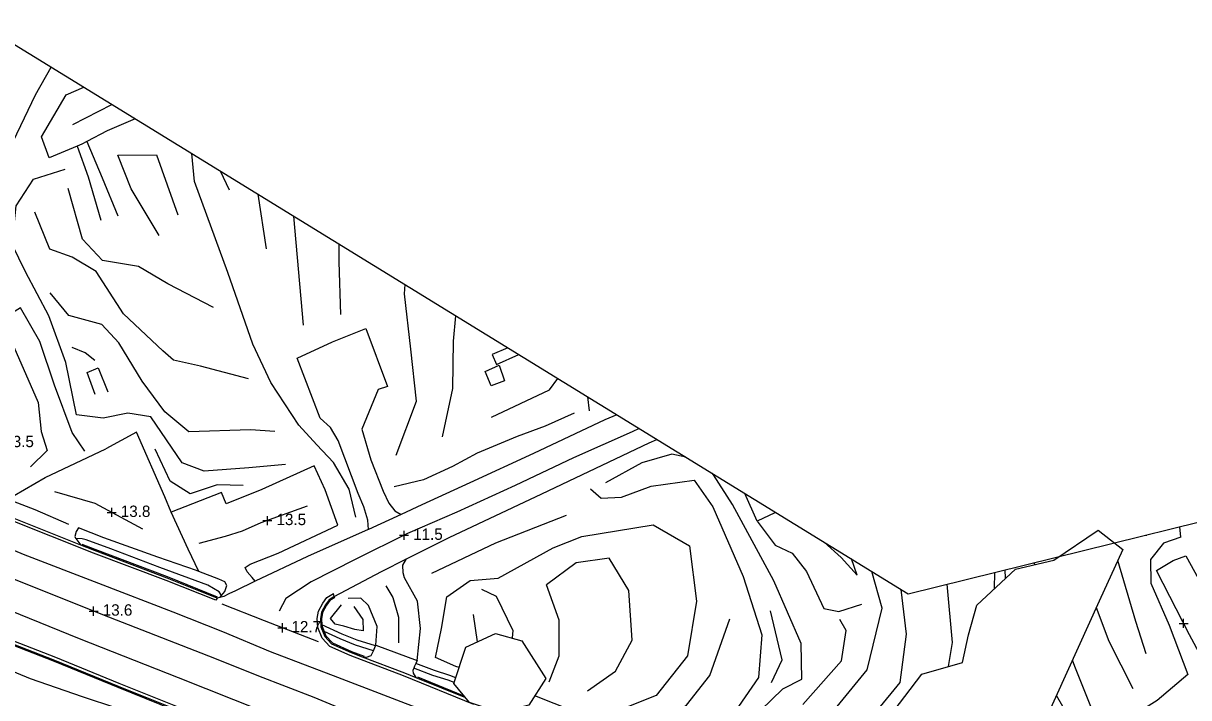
# Model space of a CAD drawing. Extents: x 2316231 to 2323598, y 363169 to 371906.
# Drawn here: x 2320328 to 2320840, y 366181 to 366478 of the extents above; entities that cross this region are included whole.
import ezdxf

# ---------------------------------------------------------------- set-up
doc = ezdxf.new("R2010")
doc.units = 0
for name, color, linetype in [('RD_DTM_BkLn1', 7, 'Continuous'), ('RD_DTM_Holes', 7, 'Continuous'), ('RD_DTM_TinHull', 7, 'Continuous'), ('RD_DTM_Void', 7, 'Continuous'), ('RD_EX_Road', 7, 'Continuous')]:
    doc.layers.add(name, color=color, linetype=linetype)

msp = doc.modelspace()

# ---------------------------------------------------------------- linework, layer by layer
at = {"layer": 'RD_DTM_BkLn1'}
for p, q in [((2320349.32, 366433.108), (2320366.601, 366441.984)), ((2320434.499, 366378.577), (2320430.846, 366402.512)), ((2320450.743, 366345.006), (2320446.543, 366392.867)), ((2320576.626, 366307.37), (2320575.799, 366313.452)), ((2320836.637, 366251.842), (2320836.128, 366256.376)), ((2320821.439, 366252.389), (2320821.41, 366252.742)), ((2320694.316, 366235.036), (2320691.728, 366242.224)), ((2320772.393, 366239.775), (2320772.082, 366240.564)), ((2320754.705, 366229.244), (2320754.75, 366236.285)), ((2320759.549, 366233.772), (2320759.337, 366237.417)), ((2320527.298, 366205.819), (2320525.602, 366217.862)), ((2320786.901, 366173.556), (2320781.929, 366182.258))]:
    msp.add_line(p, q, dxfattribs=at)
for points in [[(2320277.189, 366325.878), (2320280.846, 366330.64), (2320288.025, 366344.848), (2320297.623, 366364.721), (2320308.671, 366391.91), (2320318.365, 366415.644), (2320332.971, 366446.263), (2320339.886, 366458.398)], [(2320387.394, 366384.453), (2320375.086, 366404.966), (2320369.143, 366419.66), (2320386.201, 366419.835), (2320395.494, 366393.474)], [(2320473.779, 366260.649), (2320470.841, 366272.884), (2320464.038, 366284.668), (2320456.706, 366292.429), (2320448.785, 366301.035), (2320436.442, 366319.845), (2320428.589, 366336.629), (2320417.593, 366368.193), (2320402.945, 366408.194), (2320401.743, 366420.393)], [(2320442.845, 366283.786), (2320426.769, 366282.216), (2320407.09, 366280.857), (2320397.408, 366284.435), (2320383.722, 366304.747), (2320373.513, 366306.357), (2320362.74, 366304.098), (2320351.049, 366305.578), (2320346.306, 366328.605), (2320338.851, 366349.108), (2320328.623, 366368.37), (2320322.72, 366380.369), (2320324.435, 366397.426), (2320332.099, 366409.168), (2320345.943, 366413.554)], [(2320411.199, 366352.743), (2320391.098, 366363.078), (2320378.294, 366370.784), (2320362.48, 366373.447), (2320353.596, 366382.818), (2320347.285, 366405.074)], [(2320426.629, 366321.406), (2320405.516, 366326.963), (2320393.657, 366329.576), (2320388.913, 366333.646), (2320371.676, 366349.899), (2320359.588, 366368.532), (2320349.073, 366374.939), (2320339.25, 366378.378), (2320332.688, 366394.639)], [(2320467.272, 366349.711), (2320466.474, 366372.887), (2320466.53, 366380.587)], [(2320438.149, 366298.262), (2320427.503, 366298.999), (2320400.383, 366298.077), (2320389.896, 366306.899), (2320379.932, 366320.384), (2320369.593, 366337.161), (2320362.159, 366345.344), (2320347.567, 366349.2), (2320339.48, 366359.172)], [(2320491.593, 366287.792), (2320500.53, 366311.625), (2320498.049, 366334.404), (2320495.148, 366358.819), (2320495.499, 366362.789)], [(2320511.879, 366295.855), (2320516.528, 366317.22), (2320516.81, 366337.927), (2320517.728, 366349.131)], [(2320322.464, 366337.81), (2320334.075, 366310.991), (2320335.446, 366298.183), (2320338.166, 366289.939), (2320330.825, 366282.663)], [(2320359.006, 366329.475), (2320354.747, 366332.853), (2320349.104, 366335.108)], [(2320533.534, 366304.597), (2320558.909, 366316.545), (2320562.69, 366321.506)], [(2320569.876, 366306.332), (2320557.109, 366300.667), (2320544.699, 366296.062), (2320527.161, 366288.797), (2320516.293, 366282.863), (2320503.513, 366277.036), (2320490.729, 366273.985)], [(2320389.862, 366269.542), (2320377.375, 366297.919), (2320363.838, 366290.662)], [(2320598.434, 366299.545), (2320595.253, 366298.038), (2320569.555, 366286.652), (2320543.863, 366274.589), (2320518.256, 366262.853), (2320496.503, 366253.353), (2320473.477, 366242.054), (2320454.113, 366232.235), (2320443.025, 366224.797), (2320440.117, 366219.241)], [(2320424.314, 366274.579), (2320412.906, 366274.844), (2320400.989, 366270.807), (2320392.173, 366276.398), (2320385.549, 366290.548)], [(2320618.872, 366286.988), (2320612.698, 366288.305), (2320599.512, 366284.452), (2320583.608, 366275.671)], [(2320533.6, 366162.638), (2320506.3, 366174.535), (2320465.853, 366190.084), (2320436.355, 366201.486), (2320415.415, 366210.263), (2320393.459, 366218.872), (2320360.843, 366231.403), (2320327.669, 366244.242), (2320294.269, 366258.238), (2320257.317, 366273.156), (2320231.348, 366282.823)], [(2320577.045, 366272.997), (2320581.683, 366268.882), (2320590.588, 366269.346), (2320603.735, 366274.18), (2320622.56, 366276.839), (2320630.763, 366265.105), (2320644.145, 366234.528), (2320652.277, 366208.945), (2320650.853, 366190.101), (2320642.133, 366177.456), (2320634.842, 366163.914), (2320629.575, 366158.256)], [(2320669.911, 366189.341), (2320669.692, 366205.092), (2320657.618, 366232.545), (2320639.473, 366266.13), (2320631.058, 366279.254), (2320630.436, 366279.882)], [(2320494.149, 366165.157), (2320455.433, 366181.394), (2320431.195, 366190.66), (2320411.834, 366198.411), (2320362.627, 366217.671), (2320320.451, 366234.561), (2320272.725, 366253.73), (2320229.865, 366271.678)], [(2320380.221, 366255.304), (2320359.135, 366266.625), (2320341.46, 366271.751)], [(2320347.568, 366257.348), (2320332.785, 366263.889), (2320321.428, 366268.272)], [(2320452.391, 366265.427), (2320432.076, 366258.064), (2320423.896, 366254.434), (2320416.39, 366252.14), (2320404.772, 366248.964)], [(2320507.269, 366236.048), (2320535.337, 366249.354), (2320566.395, 366261.462)], [(2320494.89, 366150.627), (2320481.114, 366156.169), (2320463.464, 366163.302), (2320432.316, 366175.462), (2320395.909, 366189.933), (2320352.3, 366207.148), (2320312.94, 366223.086), (2320274.198, 366238.915), (2320237.981, 366253.746), (2320228.056, 366257.444)], [(2320519.241, 366194.477), (2320517.839, 366195.025), (2320508.812, 366198.914), (2320511.466, 366211.647), (2320513.766, 366225.597), (2320524.093, 366232.701), (2320536.386, 366233.795), (2320560.592, 366247.081), (2320573.262, 366252.151), (2320604.622, 366257.303), (2320620.601, 366248.036), (2320623.573, 366223.725), (2320619.71, 366199.683), (2320605.893, 366182.184), (2320590.826, 366176.244)], [(2320836.637, 366251.842), (2320828.977, 366249.188), (2320823.188, 366241.947), (2320823.338, 366231.539), (2320831.496, 366213.178), (2320839.654, 366191.504), (2320826.124, 366180.023), (2320812.449, 366171.32), (2320800.46, 366168.579), (2320790.036, 366195.04), (2320788.965, 366197.757)], [(2320423.52, 366157.007), (2320383.884, 366171.722), (2320353.642, 366181.647), (2320330.829, 366189.538), (2320309.039, 366198.519), (2320286.25, 366206.469), (2320258.731, 366217.227), (2320229.52, 366226.037), (2320188.602, 366241.122), (2320167.473, 366249.033)], [(2320585.143, 366242.608), (2320570.767, 366240.467), (2320557.728, 366230.861)], [(2320575.644, 366184.269), (2320587.965, 366192.958), (2320595.327, 366206.558), (2320593.831, 366228.327), (2320585.143, 366242.608)], [(2320821.306, 366200.508), (2320816.759, 366214.679), (2320808.86, 366241.626)], [(2320684.118, 366175.719), (2320698.663, 366193.461), (2320705.301, 366220.646), (2320700.697, 366236.714)], [(2320487.012, 366230.458), (2320490.162, 366225.245), (2320492.553, 366216.653), (2320492.546, 366205.442)], [(2320558.766, 366188.212), (2320563.207, 366199.65), (2320563.175, 366215.377), (2320557.728, 366230.861)], [(2320734.383, 366194.965), (2320736.219, 366205.524), (2320733.789, 366231.11)], [(2320529.061, 366228.945), (2320535.562, 366225.937), (2320542.832, 366210.826), (2320542.502, 366207.494)], [(2320703.263, 366175.789), (2320713.115, 366187.867), (2320715.921, 366209.139), (2320713.631, 366228.767)], [(2320457.374, 366205.846), (2320433.59, 366215.015), (2320415.055, 366222.34)], [(2320472.915, 366221.326), (2320476.83, 366215.559), (2320477.007, 366210.623), (2320473.394, 366211.173), (2320468.609, 366212.641), (2320464.73, 366213.565), (2320462.624, 366216.088), (2320467.507, 366222.098)], [(2320815.589, 366185.17), (2320805.103, 366205.939), (2320799.436, 366220.823)], [(2320604.733, 366169.498), (2320619.153, 366177.986), (2320629.474, 366191.076), (2320638.22, 366215.983)], [(2320656.543, 366187.927), (2320661.208, 366197.847), (2320656.187, 366219.43)], [(2320670.36, 366178.243), (2320687.373, 366197.435), (2320689.378, 366210.814), (2320686.67, 366215.628)], [(2320608.931, 366157.378), (2320569.481, 366175.328), (2320552.531, 366182.119)]]:
    msp.add_lwpolyline(points, dxfattribs=at)
at = {"layer": 'RD_DTM_Holes'}
for points in [[(2320743.184, 366208.848), (2320746.914, 366221.959), (2320763.81, 366237.757), (2320780.684, 366241.725), (2320800.176, 366254.868), (2320811.003, 366246.359), (2320800.733, 366223.679), (2320777.231, 366171.911), (2320759.986, 366170.011), (2320738.35, 366162.342), (2320738.441, 366149.94), (2320744.083, 366125.412), (2320726.638, 366113.037), (2320704.663, 366124.002), (2320688.271, 366139.316), (2320690.415, 366149.23), (2320722.742, 366191.581), (2320740.581, 366196.767), (2320743.184, 366208.848)], [(2320516.901, 366187.518), (2320522.26, 366203.453), (2320535.193, 366209.525), (2320546.861, 366206.283), (2320557.353, 366189.738), (2320549.875, 366177.924), (2320537.102, 366174.768), (2320523.785, 366179.153), (2320516.901, 366187.518)]]:
    msp.add_lwpolyline(points, dxfattribs=at)
at = {"layer": 'RD_DTM_TinHull'}
msp.add_lwpolyline([(2318009.783, 367630.234), (2318999.407, 367049.655), (2319281.252, 367000.442), (2319521.217, 366961.394), (2320716.689, 366226.888), (2320934.852, 366280.749), (2321141.465, 366502.562), (2321263.978, 366719.924), (2321282.537, 366948.249), (2321279.947, 367175.232), (2321214.652, 367465.641), (2321221.515, 367818.629), (2321207.427, 368150.673), (2321267.86, 368369.229), (2321400.963, 368599.408), (2321534.916, 368777.939)], dxfattribs=at)
at = {"layer": 'RD_DTM_Void'}
for p, q in [((2320364.468, 366262.688), (2320368.468, 366262.688)), ((2320366.468, 366260.688), (2320366.468, 366264.688)), ((2320434.935, 366257.101), (2320434.935, 366261.101)), ((2320432.935, 366259.101), (2320436.935, 366259.101)), ((2320493.014, 366252.623), (2320497.014, 366252.623)), ((2320495.014, 366250.623), (2320495.014, 366254.623)), ((2320358.541, 366217.307), (2320358.541, 366221.307)), ((2320356.541, 366219.307), (2320360.541, 366219.307)), ((2320837.809, 366211.929), (2320837.809, 366215.929)), ((2320439.519, 366211.958), (2320443.519, 366211.958)), ((2320441.519, 366209.958), (2320441.519, 366213.958)), ((2320835.809, 366213.929), (2320839.809, 366213.929))]:
    msp.add_line(p, q, dxfattribs=at)
at = {"layer": 'RD_EX_Road'}
for p, q in [((2320418.284, 366404.344), (2320414.34, 366412.653)), ((2320392.581, 366262.733), (2320389.862, 366269.542)), ((2320650.297, 366258.904), (2320644.831, 366271.038)), ((2320493.695, 366261.795), (2320479.345, 366255.227)), ((2320350.677, 366251.243), (2320352.897, 366248.326)), ((2320414.063, 366225.346), (2320412.795, 366225.001)), ((2320414.063, 366225.346), (2320414.747, 366226.175)), ((2320464.288, 366225.737), (2320463.983, 366227.116)), ((2320481.601, 366201.916), (2320482.451, 366204.017)), ((2320482.451, 366204.017), (2320482.611, 366204.413)), ((2320482.611, 366204.413), (2320500.776, 366197.534)), ((2320500.776, 366197.534), (2320500.18, 366196.285)), ((2320500.196, 366190.152), (2320522.018, 366181.299)), ((2320500.888, 366190.411), (2320521.352, 366182.109))]:
    msp.add_line(p, q, dxfattribs=at)
for points in [[(2320351.281, 366423.711), (2320338.93, 366418.513), (2320335.645, 366427.764), (2320346.458, 366446.287), (2320354.204, 366449.601)], [(2320376.776, 366435.733), (2320364.503, 366430.449), (2320355.485, 366425.707)], [(2320355.485, 366425.707), (2320353.333, 366424.575), (2320351.281, 366423.711)], [(2320355.485, 366425.707), (2320362.285, 366409.674), (2320369.194, 366393.083)], [(2320351.281, 366423.711), (2320356.081, 366410.136), (2320361.668, 366391.139)], [(2320354.65, 366289.651), (2320349.047, 366297.775), (2320341.291, 366318.583), (2320334.877, 366337.807), (2320326.322, 366352.612), (2320316.094, 366346.301), (2320305.035, 366336.355), (2320295.267, 366318.851), (2320297.449, 366305.221), (2320302.814, 366291.266), (2320304.187, 366282.297), (2320314.044, 366276.909), (2320323.194, 366274)], [(2320479.345, 366255.227), (2320479.078, 366259.236), (2320477.31, 366265.163), (2320474.877, 366271.048), (2320466.018, 366294.326), (2320462.638, 366299.996), (2320458.21, 366304.109), (2320447.995, 366330.511), (2320463.596, 366337.731), (2320478.208, 366343.488), (2320487.752, 366318.059), (2320483.648, 366316.757), (2320476.412, 366299.306), (2320480.368, 366285.804), (2320485.816, 366272.058), (2320488.404, 366266.744), (2320490.901, 366263.343), (2320493.695, 366261.795)], [(2320540.605, 366335.075), (2320533.803, 366332.047), (2320535.675, 366327.683), (2320545.479, 366332.081)], [(2320359.184, 366314.575), (2320355.714, 366324.154), (2320360.547, 366326.221), (2320364.71, 366315.693)], [(2320536.875, 366327.359), (2320539.15, 366320.577), (2320533.289, 366318.272), (2320530.743, 366324.683), (2320536.875, 366327.359)], [(2320588.51, 366305.642), (2320583.366, 366303.416), (2320551.94, 366288.628), (2320523.897, 366275.671), (2320502.889, 366266.003), (2320493.695, 366261.795)], [(2320412.795, 366225.001), (2320412.22, 366224.168), (2320390.38, 366232.729), (2320358.531, 366244.789), (2320320.996, 366259.746), (2320285.905, 366273.683), (2320249.677, 366288.666), (2320233.465, 366295.751)], [(2320496.066, 366242.218), (2320514.925, 366251.734), (2320555.657, 366270.904), (2320602.827, 366293.273), (2320606.2, 366294.773)], [(2320320.467, 366268.99), (2320323.541, 366270.124), (2320337.21, 366277.999), (2320363.838, 366290.662)], [(2320429.544, 366232.52), (2320428.202, 366234.151), (2320426.013, 366236.534), (2320425.222, 366238.534), (2320427.379, 366240.001), (2320439.685, 366244.759), (2320465.937, 366257.028), (2320460.281, 366272.641), (2320455.511, 366283.093), (2320432.538, 366272.715), (2320416.803, 366266.487), (2320414.819, 366271.401), (2320392.581, 366262.733)], [(2320352.897, 366248.326), (2320321.44, 366260.861), (2320308.007, 366266.196)], [(2320404.757, 366236.772), (2320400.124, 366246.605), (2320392.581, 366262.733)], [(2320658.385, 366262.711), (2320658.01, 366262.456), (2320650.297, 366258.904)], [(2320404.757, 366236.772), (2320403.781, 366237.153), (2320386.741, 366242.998), (2320363.046, 366251.572), (2320351.864, 366255.977), (2320350.861, 366254.269), (2320350.285, 366252.032), (2320350.619, 366251.318), (2320350.677, 366251.243)], [(2320650.297, 366258.904), (2320658.193, 366248.245), (2320665.612, 366244.764), (2320671.95, 366236.659), (2320679.633, 366220.483), (2320686.227, 366219.084), (2320696.376, 366222.317)], [(2320414.747, 366226.175), (2320413.668, 366227.752), (2320408.788, 366230.655), (2320387.584, 366238.43), (2320366.104, 366246.616), (2320355.199, 366250.587), (2320353.558, 366251.135), (2320350.677, 366251.243)], [(2320479.345, 366255.227), (2320479.307, 366255.209), (2320452.497, 366243.376), (2320429.544, 366232.52)], [(2320412.795, 366225.001), (2320390.817, 366233.847), (2320358.966, 366245.908), (2320352.897, 366248.326)], [(2320412.982, 366225.464), (2320390.999, 366234.313), (2320359.147, 366246.374), (2320353.5, 366248.624)], [(2320679.794, 366249.557), (2320687.182, 366242.808), (2320694.316, 366235.036)], [(2320226.91, 366242.216), (2320239.508, 366237.192), (2320272.574, 366224.426), (2320304.218, 366211.621), (2320341.194, 366197.241), (2320369.107, 366185.853), (2320411.57, 366168.806), (2320447.49, 366154.754)], [(2320226.946, 366242.74), (2320239.691, 366237.657), (2320272.758, 366224.891), (2320304.402, 366212.086), (2320341.379, 366197.705), (2320369.295, 366186.317), (2320411.754, 366169.271), (2320447.674, 366155.219)], [(2320448.042, 366156.149), (2320412.238, 366170.478), (2320369.782, 366187.522), (2320341.86, 366198.913), (2320304.882, 366213.294), (2320273.236, 366226.1), (2320240.166, 366238.868), (2320227.038, 366244.103)], [(2320464.288, 366225.737), (2320485.177, 366236.724), (2320496.066, 366242.218)], [(2320500.776, 366197.534), (2320502.319, 366211.698), (2320500.978, 366223.712), (2320495.25, 366233.925), (2320494.623, 366236.064), (2320494.529, 366239.495), (2320496.066, 366242.218)], [(2320851.985, 366186.238), (2320849.942, 366191.2), (2320840.345, 366208.953), (2320825.944, 366237.203), (2320833.219, 366241.564), (2320838.821, 366243.614), (2320850.781, 366221.726), (2320861.571, 366202.694), (2320867.629, 366196.662)], [(2320414.747, 366226.175), (2320416.178, 366227.91), (2320417.036, 366230.599), (2320416.207, 366232.226), (2320413.636, 366233.305), (2320404.757, 366236.772)], [(2320429.544, 366232.52), (2320420.846, 366228.181), (2320418.014, 366226.905), (2320415.732, 366225.801), (2320414.063, 366225.346)], [(2320525.687, 366178.3), (2320494.71, 366190.867), (2320471.263, 366199.836), (2320462.353, 366203.747), (2320458.995, 366207.468), (2320457.102, 366212.124), (2320456.848, 366216.034), (2320457.384, 366219.286), (2320459.24, 366222.866), (2320461.065, 366225.316), (2320463.983, 366227.116)], [(2320464.288, 366225.737), (2320462.081, 366224.336), (2320460.431, 366222.121), (2320458.729, 366218.839), (2320458.256, 366215.965), (2320458.484, 366212.441), (2320460.199, 366208.223), (2320463.191, 366204.908), (2320471.794, 366201.131), (2320476.648, 366199.275)], [(2320464.556, 366225.315), (2320462.427, 366223.963), (2320460.856, 366221.855), (2320459.21, 366218.679), (2320458.759, 366215.94), (2320458.932, 366213.257)], [(2320482.611, 366204.413), (2320483.18, 366212.552), (2320479.463, 366221.83), (2320476.031, 366224.945), (2320470.454, 366224.878)], [(2320458.932, 366213.257), (2320458.978, 366212.554), (2320459.877, 366210.342)], [(2320482.451, 366204.017), (2320474.389, 366206.516), (2320467.824, 366209.194), (2320458.932, 366213.257)], [(2320459.877, 366210.342), (2320460.629, 366208.493), (2320463.49, 366205.322), (2320471.984, 366201.594), (2320477.494, 366199.486)], [(2320481.601, 366201.916), (2320473.627, 366204.388), (2320466.928, 366207.12), (2320459.877, 366210.342)], [(2320476.648, 366199.275), (2320478.491, 366199.074), (2320480.596, 366199.795), (2320481.472, 366201.597), (2320481.601, 366201.916)], [(2320476.648, 366199.275), (2320495.223, 366192.169), (2320500.196, 366190.152)], [(2320500.18, 366196.285), (2320499.616, 366195.103), (2320499.288, 366194.207)], [(2320517.755, 366190.059), (2320515.11, 366191.068), (2320508.4, 366193.208), (2320500.18, 366196.285)], [(2320499.288, 366194.207), (2320498.914, 366193.183), (2320499.034, 366192.015), (2320500.196, 366190.152)], [(2320517.035, 366187.918), (2320514.408, 366188.921), (2320507.661, 366191.073), (2320499.288, 366194.207)], [(2320642.868, 366164.721), (2320651.734, 366175.663), (2320661.587, 366185.128), (2320669.911, 366189.341)]]:
    msp.add_lwpolyline(points, dxfattribs=at)

# ---------------------------------------------------------------- texts
at = {"layer": 'RD_DTM_Void'}
for s, p in [('13.5', (2320319.25, 366291.365)), ('13.8', (2320370.468, 366260.688)), ('13.5', (2320438.935, 366257.101)), ('11.5', (2320499.014, 366250.623)), ('13.6', (2320362.541, 366217.307)), ('12.7', (2320445.519, 366209.958))]:
    msp.add_text(s, height=5, dxfattribs=at).set_placement(p)

doc.saveas('drawing.dxf')
